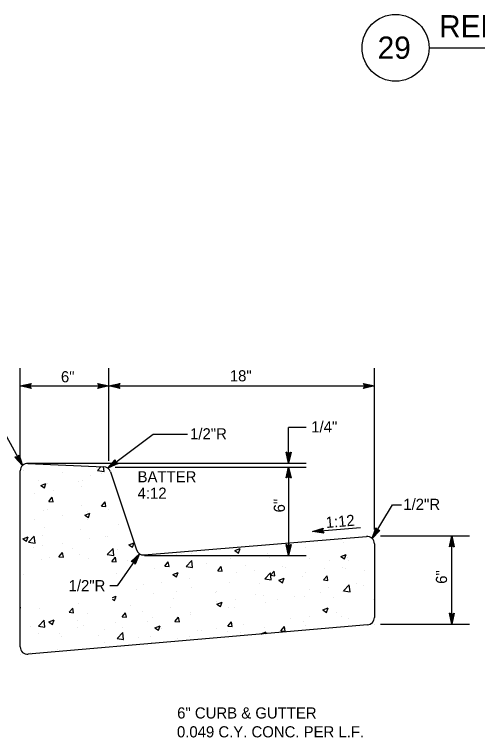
# Model space of a CAD drawing. Extents: x -119017 to -116080, y -104449 to -102845.
# Drawn here: x -118067.3 to -117818, y -104028.1 to -103638.5 of the extents above; entities that cross this region are included whole.
import ezdxf

# ---------------------------------------------------------------- set-up
doc = ezdxf.new("R2010")
doc.units = 0
for name, color, linetype in [('G-MARK', 7, 'Continuous'), ('G-TEXT', 7, 'Continuous'), ('Misc CnstDet(22)', 7, 'Continuous'), ('Nongeo Data(60)', 7, 'Continuous')]:
    doc.layers.add(name, color=color, linetype=linetype)

msp = doc.modelspace()

# ---------------------------------------------------------------- linework, layer by layer
at = {"layer": 'G-MARK'}
for p, q in [((-118064.22, -103876.84), (-118064.22, -103829.12)), ((-118016.53, -103879.03), (-118016.53, -103829.12)), ((-117873.56, -103916.09), (-117873.56, -103829.12)), ((-118064.22, -103838.66), (-118016.53, -103838.66)), ((-118016.53, -103838.66), (-117873.56, -103838.66)), ((-117919.75, -103880.19), (-117919.75, -103861.11)), ((-117910.24, -103861.11), (-117919.75, -103861.11)), ((-118060.88, -103880.19), (-117910.24, -103880.19)), ((-118013.19, -103882.35), (-117910.24, -103882.35)), ((-117919.75, -103882.35), (-117919.75, -103901.42)), ((-117919.75, -103891.88), (-117919.75, -103930)), ((-117906.83, -103917.18), (-117880.97, -103915.03)), ((-117870.22, -103919.4), (-117822.37, -103919.4)), ((-117831.88, -103967.06), (-117831.88, -103919.4)), ((-117997.3, -103930), (-117910.24, -103930)), ((-117870.22, -103967.06), (-117822.37, -103967.06))]:
    msp.add_line(p, q, dxfattribs=at)
for points in [[(-118063.03, -103881.5), (-118077.01, -103856.14), (-118081.48, -103856.14)], [(-118017.03, -103883.04), (-117992.64, -103864.59), (-117974.26, -103864.59)], [(-117874.84, -103920.81), (-117863.9, -103902.7), (-117858.93, -103902.7)], [(-118000.05, -103929.1), (-118012.09, -103946.39), (-118016.06, -103946.39)]]:
    msp.add_lwpolyline(points, dxfattribs=at)
at = {"layer": 'G-TEXT'}
for points in [[(-118058.32, -103839.98), (-118064.22, -103838.66), (-118058.32, -103837.35), (-118058.53, -103837.7), (-118062.85, -103838.66), (-118058.53, -103839.63), (-118058.73, -103839.28), (-118061.5, -103838.66), (-118058.74, -103838.05), (-118058.95, -103838.4), (-118060.14, -103838.66), (-118058.94, -103838.93), (-118059.1, -103838.66), (-118058.32, -103837.35), (-118059.1, -103838.66)], [(-118022.44, -103837.34), (-118016.53, -103838.66), (-118022.44, -103839.97), (-118022.23, -103839.62), (-118017.9, -103838.66), (-118022.23, -103837.69), (-118022.02, -103838.04), (-118019.25, -103838.66), (-118022.02, -103839.27), (-118021.81, -103838.92), (-118020.61, -103838.66), (-118021.81, -103838.39), (-118021.65, -103838.66), (-118022.44, -103839.97), (-118021.65, -103838.66)], [(-118010.63, -103839.98), (-118016.53, -103838.66), (-118010.63, -103837.35), (-118010.84, -103837.7), (-118015.16, -103838.66), (-118010.84, -103839.63), (-118011.05, -103839.28), (-118013.81, -103838.66), (-118011.05, -103838.05), (-118011.26, -103838.4), (-118012.45, -103838.66), (-118011.25, -103838.93), (-118011.42, -103838.66), (-118010.63, -103837.35), (-118011.42, -103838.66)], [(-117879.47, -103837.34), (-117873.56, -103838.66), (-117879.47, -103839.97), (-117879.26, -103839.62), (-117874.93, -103838.66), (-117879.26, -103837.69), (-117879.05, -103838.04), (-117876.28, -103838.66), (-117879.05, -103839.27), (-117878.84, -103838.92), (-117877.64, -103838.66), (-117878.84, -103838.39), (-117878.68, -103838.66), (-117879.47, -103839.97), (-117878.68, -103838.66)], [(-117918.43, -103874.28), (-117919.75, -103880.19), (-117921.06, -103874.28), (-117920.71, -103874.49), (-117919.75, -103878.82), (-117918.78, -103874.49), (-117919.13, -103874.7), (-117919.75, -103877.47), (-117920.36, -103874.7), (-117920.01, -103874.91), (-117919.75, -103876.11), (-117919.48, -103874.91), (-117919.75, -103875.07), (-117921.06, -103874.28), (-117919.75, -103875.07)], [(-118064.79, -103875.71), (-118063.03, -103881.5), (-118067.08, -103877.01), (-118066.67, -103877.02), (-118063.71, -103880.31), (-118065, -103876.07), (-118065.2, -103876.42), (-118064.37, -103879.14), (-118066.27, -103877.03), (-118065.86, -103877.04), (-118065.04, -103877.95), (-118065.4, -103876.77), (-118065.55, -103877.05), (-118067.08, -103877.01), (-118065.55, -103877.05)], [(-118011.55, -103880.48), (-118017.03, -103883.04), (-118013.15, -103878.39), (-118013.11, -103878.8), (-118015.95, -103882.2), (-118011.93, -103880.33), (-118012.31, -103880.18), (-118014.88, -103881.38), (-118013.06, -103879.2), (-118013.01, -103879.61), (-118013.8, -103880.55), (-118012.69, -103880.03), (-118012.98, -103879.91), (-118013.15, -103878.39), (-118012.98, -103879.91)], [(-117921.07, -103888.25), (-117919.75, -103882.35), (-117918.44, -103888.25), (-117918.79, -103888.04), (-117919.75, -103883.72), (-117920.72, -103888.04), (-117920.37, -103887.84), (-117919.75, -103885.07), (-117919.14, -103887.83), (-117919.49, -103887.62), (-117919.75, -103886.43), (-117920.02, -103887.63), (-117919.75, -103887.47), (-117918.44, -103888.25), (-117919.75, -103887.47)], [(-117900.83, -103917.93), (-117906.83, -103917.18), (-117901.08, -103915.31), (-117901.26, -103915.68), (-117905.47, -103917.05), (-117901.07, -103917.6), (-117901.31, -103917.27), (-117904.13, -103916.92), (-117901.43, -103916.05), (-117901.61, -103916.42), (-117902.77, -103916.79), (-117901.55, -103916.95), (-117901.74, -103916.69), (-117901.08, -103915.31), (-117901.74, -103916.69)], [(-117870.62, -103916.48), (-117874.84, -103920.81), (-117872.85, -103915.1), (-117872.67, -103915.46), (-117874.13, -103919.64), (-117871.02, -103916.47), (-117871.43, -103916.47), (-117873.41, -103918.5), (-117872.48, -103915.82), (-117872.29, -103916.19), (-117872.7, -103917.34), (-117871.84, -103916.46), (-117872.15, -103916.46), (-117872.85, -103915.1), (-117872.15, -103916.46)], [(-117833.2, -103925.31), (-117831.88, -103919.4), (-117830.57, -103925.31), (-117830.92, -103925.1), (-117831.87, -103920.77), (-117832.85, -103925.1), (-117832.5, -103924.89), (-117831.88, -103922.12), (-117831.27, -103924.89), (-117831.62, -103924.68), (-117831.88, -103923.48), (-117832.15, -103924.68), (-117831.88, -103924.52), (-117830.57, -103925.31), (-117831.88, -103924.52)], [(-117918.43, -103924.1), (-117919.75, -103930), (-117921.06, -103924.1), (-117920.71, -103924.31), (-117919.75, -103928.64), (-117918.78, -103924.31), (-117919.13, -103924.52), (-117919.75, -103927.29), (-117920.36, -103924.52), (-117920.01, -103924.73), (-117919.75, -103925.93), (-117919.48, -103924.72), (-117919.75, -103924.89), (-117921.06, -103924.1), (-117919.75, -103924.89)], [(-118004.48, -103933.22), (-118000.05, -103929.1), (-118002.32, -103934.71), (-118002.49, -103934.34), (-118000.83, -103930.23), (-118004.08, -103933.25), (-118003.67, -103933.27), (-118001.59, -103931.34), (-118002.65, -103933.97), (-118002.82, -103933.6), (-118002.36, -103932.46), (-118003.27, -103933.3), (-118002.95, -103933.32), (-118002.32, -103934.71), (-118002.95, -103933.32)], [(-117830.56, -103961.16), (-117831.88, -103967.06), (-117833.19, -103961.15), (-117832.84, -103961.37), (-117831.88, -103965.69), (-117830.91, -103961.36), (-117831.26, -103961.57), (-117831.88, -103964.34), (-117832.49, -103961.57), (-117832.14, -103961.79), (-117831.87, -103962.98), (-117831.61, -103961.78), (-117831.88, -103961.94), (-117833.19, -103961.15), (-117831.88, -103961.94)]]:
    msp.add_lwpolyline(points, close=True, dxfattribs=at)
at = {"layer": 'Misc CnstDet(22)'}
for p, q in [((-118016.53, -103838.66), (-118016.53, -103838.66)), ((-117873.56, -103838.66), (-117873.56, -103838.66)), ((-118064.22, -103880.19), (-118064.22, -103880.19)), ((-118064.22, -103880.19), (-118064.22, -103880.19)), ((-118064.22, -103880.19), (-118064.22, -103880.19)), ((-118022.63, -103884.16), (-118020.69, -103882.16)), ((-118019.1, -103884.69), (-118019.38, -103882.22)), ((-118016.53, -103882.35), (-118016.53, -103882.35)), ((-118016.53, -103882.35), (-118016.53, -103882.35)), ((-118016.53, -103882.35), (-118016.53, -103882.35)), ((-118016.53, -103882.35), (-118016.53, -103882.35)), ((-117919.75, -103882.35), (-117919.75, -103882.35)), ((-118062.66, -103884.16), (-118062.66, -103884.16)), ((-118041.46, -103885.07), (-118041.46, -103885.07)), ((-118022.63, -103884.16), (-118019.1, -103884.69)), ((-118020.25, -103885.97), (-118020.25, -103885.97)), ((-118054.28, -103889.51), (-118054.28, -103889.51)), ((-118030.61, -103889.7), (-118030.61, -103889.7)), ((-118026.38, -103887.1), (-118026.38, -103887.1)), ((-118053.15, -103892.23), (-118050.37, -103891.17)), ((-118053.15, -103892.23), (-118051.18, -103893.57)), ((-118051.24, -103892.7), (-118051.24, -103892.7)), ((-118051.18, -103893.57), (-118050.37, -103891.17)), ((-118049.56, -103891.07), (-118049.56, -103891.07)), ((-118033.08, -103890.38), (-118033.08, -103890.38)), ((-118031.29, -103893.07), (-118031.29, -103893.07)), ((-118056.28, -103896.39), (-118056.28, -103896.39)), ((-118046.34, -103895.07), (-118046.34, -103895.07)), ((-118048.9, -103900.86), (-118046.99, -103898.58)), ((-118048.9, -103900.86), (-118046.52, -103901.08)), ((-118046.52, -103901.08), (-118046.99, -103898.58)), ((-118020.41, -103903.36), (-118018.5, -103901.08)), ((-118018.07, -103903.58), (-118018.5, -103901.08)), ((-118010.72, -103900.14), (-118010.72, -103900.14)), ((-118051.75, -103905.89), (-118051.75, -103905.89)), ((-118049.37, -103905.24), (-118049.37, -103905.24)), ((-118031.11, -103902.92), (-118031.11, -103902.92)), ((-118020.41, -103903.36), (-118018.07, -103903.58)), ((-118016.66, -103905.46), (-118016.66, -103905.46)), ((-118041.74, -103908.74), (-118041.74, -103908.74)), ((-118029.45, -103908.24), (-118026.67, -103907.18)), ((-118029.45, -103908.24), (-118027.48, -103909.55)), ((-118028.17, -103906.14), (-118028.17, -103906.14)), ((-118027.48, -103909.55), (-118026.67, -103907.18)), ((-118056.78, -103910.74), (-118056.78, -103910.74)), ((-118028.01, -103910.8), (-118028.01, -103910.8)), ((-118011.19, -103913.34), (-118011.19, -103913.34)), ((-118051.18, -103914.78), (-118051.18, -103914.78)), ((-118031.58, -103916.15), (-118031.58, -103916.15)), ((-118062.82, -103921.03), (-118060.03, -103919.97)), ((-118062.82, -103921.03), (-118060.85, -103922.37)), ((-118060.85, -103922.37), (-118060.03, -103919.97)), ((-118059.75, -103922.84), (-118056.65, -103919.62)), ((-118056.22, -103923.41), (-118056.65, -103919.62)), ((-118052.21, -103919.12), (-118052.21, -103919.12)), ((-118027.1, -103921.12), (-118027.1, -103921.12)), ((-118018.5, -103919.53), (-118018.5, -103919.53)), ((-118017.16, -103919.81), (-118017.16, -103919.81)), ((-117873.56, -103919.4), (-117873.56, -103919.4)), ((-117873.56, -103919.4), (-117873.56, -103919.4)), ((-117831.88, -103919.4), (-117831.88, -103919.4)), ((-118059.75, -103922.84), (-118056.22, -103923.41)), ((-118052.18, -103924.41), (-118052.18, -103924.41)), ((-118041.68, -103923.5), (-118041.68, -103923.5)), ((-118005.75, -103924.22), (-118002.96, -103923.16)), ((-118005.75, -103924.22), (-118003.78, -103925.56)), ((-118003.78, -103925.56), (-118002.96, -103923.16)), ((-117890.01, -103923.16), (-117890.01, -103923.16)), ((-118057.09, -103925.53), (-118057.09, -103925.53)), ((-118043.4, -103930.75), (-118041.49, -103928.47)), ((-118041.02, -103930.94), (-118041.49, -103928.47)), ((-118035.89, -103926.44), (-118035.89, -103926.44)), ((-118017.35, -103929.41), (-118014.25, -103926.19)), ((-118014.69, -103927.35), (-118014.69, -103927.35)), ((-118013.81, -103929.97), (-118014.25, -103926.19)), ((-118011.69, -103926.56), (-118011.69, -103926.56)), ((-117977.54, -103928.88), (-117977.54, -103928.88)), ((-117972.28, -103929.13), (-117972.28, -103929.13)), ((-117962.5, -103926.91), (-117962.5, -103926.91)), ((-117948.68, -103927.41), (-117945.89, -103926.35)), ((-117948.68, -103927.41), (-117946.71, -103928.72)), ((-117946.71, -103928.72), (-117945.89, -103926.35)), ((-117931.04, -103928.94), (-117931.04, -103928.94)), ((-117910.4, -103925.97), (-117910.4, -103925.97)), ((-118052.68, -103932.35), (-118052.68, -103932.35)), ((-118048.71, -103930.88), (-118048.71, -103930.88)), ((-118043.4, -103930.75), (-118041.02, -103930.94)), ((-118032.08, -103929.38), (-118032.08, -103929.38)), ((-118027.51, -103931.79), (-118027.51, -103931.79)), ((-118017.35, -103929.41), (-118013.81, -103929.97)), ((-118014.91, -103933.23), (-118013, -103930.94)), ((-118014.91, -103933.23), (-118012.53, -103933.44)), ((-118012.53, -103933.44), (-118013, -103930.94)), ((-118006.34, -103932.66), (-118006.34, -103932.66)), ((-118000.65, -103930), (-118000.65, -103930)), ((-117987.48, -103930.19), (-117987.48, -103930.19)), ((-117980.17, -103929.44), (-117980.17, -103929.44)), ((-117974.97, -103935.98), (-117971.88, -103932.76)), ((-117971.44, -103936.54), (-117971.88, -103932.76)), ((-117951.08, -103930.04), (-117951.08, -103930.04)), ((-117951.08, -103931.47), (-117951.08, -103931.47)), ((-117929.88, -103930.91), (-117929.88, -103930.91)), ((-117919.75, -103930), (-117919.75, -103930)), ((-117908.71, -103931.82), (-117908.71, -103931.82)), ((-117897.8, -103932.66), (-117897.8, -103932.66)), ((-117891.61, -103930.57), (-117888.82, -103929.5)), ((-117891.61, -103930.57), (-117889.6, -103931.91)), ((-117889.6, -103931.91), (-117888.82, -103929.5)), ((-117887.85, -103931.35), (-117887.85, -103931.35)), ((-117887.51, -103932.72), (-117887.51, -103932.72)), ((-118012.56, -103933.48), (-118012.56, -103933.48)), ((-118003.34, -103933.41), (-118003.34, -103933.41)), ((-117986.42, -103935.73), (-117984.51, -103933.44)), ((-117986.42, -103935.73), (-117984.04, -103935.95)), ((-117985.14, -103933.57), (-117985.14, -103933.57)), ((-117984.04, -103935.95), (-117984.51, -103933.44)), ((-117974.97, -103935.98), (-117971.44, -103936.54)), ((-117971.47, -103934.26), (-117971.47, -103934.26)), ((-117963.94, -103934.48), (-117963.94, -103934.48)), ((-117957.93, -103938.23), (-117956.02, -103935.95)), ((-117955.55, -103938.42), (-117956.02, -103935.95)), ((-117942.73, -103935.35), (-117942.73, -103935.35)), ((-117922.88, -103935.98), (-117922.88, -103935.98)), ((-117921.53, -103936.26), (-117921.53, -103936.26)), ((-117900.33, -103937.13), (-117900.33, -103937.13)), ((-117890.48, -103936.38), (-117890.48, -103936.38)), ((-118062.63, -103940.07), (-118062.63, -103940.07)), ((-118012.16, -103939.79), (-118012.16, -103939.79)), ((-117992.11, -103937.26), (-117992.11, -103937.26)), ((-117982.04, -103940.2), (-117979.26, -103939.14)), ((-117982.04, -103940.2), (-117980.07, -103941.54)), ((-117980.07, -103941.54), (-117979.26, -103939.14)), ((-117957.93, -103938.23), (-117955.55, -103938.42)), ((-117947.86, -103939.26), (-117947.86, -103939.26)), ((-117937.92, -103937.95), (-117937.92, -103937.95)), ((-117932.57, -103942.58), (-117929.51, -103939.35)), ((-117929.07, -103943.11), (-117929.51, -103939.35)), ((-117929.44, -103940.7), (-117927.54, -103938.42)), ((-117929.44, -103940.7), (-117927.1, -103940.92)), ((-117927.1, -103940.92), (-117927.54, -103938.42)), ((-117910.87, -103939.17), (-117910.87, -103939.17)), ((-117900.99, -103943.2), (-117899.05, -103940.92)), ((-117898.61, -103943.42), (-117899.05, -103940.92)), ((-117889.17, -103937.23), (-117889.17, -103937.23)), ((-117879.13, -103938.04), (-117879.13, -103938.04)), ((-117987.98, -103944.55), (-117987.98, -103944.55)), ((-117972.94, -103942.54), (-117972.94, -103942.54)), ((-117951.55, -103944.7), (-117951.55, -103944.7)), ((-117932.57, -103942.58), (-117929.07, -103943.11)), ((-117931.51, -103942.17), (-117931.51, -103942.17)), ((-117924.97, -103943.39), (-117922.19, -103942.33)), ((-117924.97, -103943.39), (-117923, -103944.73)), ((-117923, -103944.73), (-117922.19, -103942.33)), ((-117912.34, -103941.2), (-117912.34, -103941.2)), ((-117900.99, -103943.2), (-117898.61, -103943.42)), ((-118001.4, -103948.42), (-118001.4, -103948.42)), ((-117997.93, -103945.86), (-117997.93, -103945.86)), ((-117971.97, -103947.48), (-117971.97, -103947.48)), ((-117935.51, -103945.2), (-117935.51, -103945.2)), ((-117908.24, -103948.33), (-117908.24, -103948.33)), ((-117898.3, -103947.02), (-117898.3, -103947.02)), ((-117890.2, -103949.14), (-117887.1, -103945.92)), ((-117886.66, -103949.67), (-117887.1, -103945.92)), ((-117883.26, -103945.05), (-117883.26, -103945.05)), ((-117879.66, -103945.95), (-117879.66, -103945.95)), ((-118014.53, -103952.68), (-118012.62, -103951.96)), ((-118013.44, -103954.36), (-118012.62, -103951.96)), ((-117992.58, -103950.46), (-117992.58, -103950.46)), ((-117980.2, -103949.33), (-117980.2, -103949.33)), ((-117958.99, -103950.21), (-117958.99, -103950.21)), ((-117958.65, -103949.17), (-117958.65, -103949.17)), ((-117937.79, -103951.11), (-117937.79, -103951.11)), ((-117933.32, -103951.64), (-117933.32, -103951.64)), ((-117916.59, -103951.99), (-117916.59, -103951.99)), ((-117911.37, -103952.39), (-117911.37, -103952.39)), ((-117902.83, -103949.92), (-117902.83, -103949.92)), ((-117890.98, -103949.61), (-117890.98, -103949.61)), ((-117890.2, -103949.14), (-117886.66, -103949.67)), ((-118033.04, -103955.8), (-118033.04, -103955.8)), ((-118014.53, -103953.61), (-118013.44, -103954.36)), ((-118012.66, -103953.02), (-118012.66, -103953.02)), ((-117981.82, -103953.15), (-117981.82, -103953.15)), ((-117958.34, -103956.21), (-117955.55, -103955.15)), ((-117958.34, -103956.21), (-117956.37, -103957.52)), ((-117958.31, -103954.93), (-117958.31, -103954.93)), ((-117956.37, -103957.52), (-117955.55, -103955.15)), ((-117948.36, -103953.61), (-117948.36, -103953.61)), ((-117931.98, -103955.37), (-117931.98, -103955.37)), ((-117925.97, -103953.9), (-117925.97, -103953.9)), ((-117895.39, -103952.89), (-117895.39, -103952.89)), ((-117874.19, -103953.8), (-117874.19, -103953.8)), ((-118064, -103958.34), (-118064.22, -103957.12)), ((-118064.22, -103958.3), (-118064, -103958.34)), ((-118053.65, -103958.77), (-118053.65, -103958.77)), ((-118037.89, -103960.62), (-118035.98, -103958.34)), ((-118035.52, -103960.84), (-118035.98, -103958.34)), ((-118004.96, -103957.12), (-118004.96, -103957.12)), ((-117998.43, -103960.21), (-117998.43, -103960.21)), ((-117983.39, -103958.21), (-117983.39, -103958.21)), ((-117952.05, -103957.93), (-117952.05, -103957.93)), ((-117949.14, -103957.9), (-117949.14, -103957.9)), ((-117901.27, -103959.37), (-117898.48, -103958.3)), ((-117901.27, -103959.37), (-117899.27, -103960.71)), ((-117899.27, -103960.71), (-117898.48, -103958.3)), ((-118037.89, -103960.62), (-118035.52, -103960.84)), ((-118028.14, -103961.09), (-118028.14, -103961.09)), ((-118009.4, -103963.12), (-118007.5, -103960.84)), ((-118009.4, -103963.12), (-118007.03, -103963.31)), ((-118008.37, -103961.53), (-118008.37, -103961.53)), ((-118007.03, -103963.31), (-118007.5, -103960.84)), ((-117993.08, -103963.68), (-117993.08, -103963.68)), ((-117980.92, -103965.59), (-117979.01, -103963.31)), ((-117978.54, -103965.81), (-117979.01, -103963.31)), ((-117972.44, -103960.71), (-117972.44, -103960.71)), ((-117972.32, -103961.87), (-117972.32, -103961.87)), ((-117918.69, -103964), (-117918.69, -103964)), ((-117908.74, -103962.68), (-117908.74, -103962.68)), ((-117893.7, -103960.71), (-117893.7, -103960.71)), ((-117891.45, -103962.81), (-117891.45, -103962.81)), ((-117887.67, -103963.84), (-117887.67, -103963.84)), ((-118058.44, -103968.09), (-118058.44, -103968.09)), ((-118054.47, -103968.09), (-118051.37, -103964.87)), ((-118054.47, -103968.09), (-118050.93, -103968.66)), ((-118051.53, -103966.94), (-118051.53, -103966.94)), ((-118050.93, -103968.66), (-118051.37, -103964.87)), ((-118051.31, -103965.06), (-118051.31, -103965.06)), ((-118048.77, -103965.84), (-118045.99, -103964.75)), ((-118048.77, -103965.84), (-118046.8, -103967.15)), ((-118048.49, -103966.78), (-118048.49, -103966.78)), ((-118046.8, -103967.15), (-118045.99, -103964.75)), ((-118033.45, -103964.81), (-118033.45, -103964.81)), ((-118030.32, -103967.81), (-118030.32, -103967.81)), ((-118013.13, -103966.25), (-118013.13, -103966.25)), ((-117995.46, -103965.84), (-117995.46, -103965.84)), ((-117991.7, -103969), (-117988.92, -103967.94)), ((-117989.73, -103970.34), (-117988.92, -103967.94)), ((-117980.92, -103965.59), (-117978.54, -103965.81)), ((-117952.43, -103968.09), (-117950.52, -103965.81)), ((-117952.43, -103968.09), (-117950.05, -103968.31)), ((-117950.05, -103968.31), (-117950.52, -103965.81)), ((-117943.77, -103967.28), (-117943.77, -103967.28)), ((-117911.84, -103965.62), (-117911.84, -103965.62)), ((-117910.81, -103967.81), (-117910.81, -103967.81)), ((-117873.56, -103967.06), (-117873.56, -103967.06)), ((-118054.15, -103972), (-118054.15, -103972)), ((-118033.51, -103969.03), (-118033.51, -103969.03)), ((-118018.63, -103969.81), (-118018.63, -103969.81)), ((-118012.09, -103974.69), (-118009, -103971.47)), ((-118009.12, -103968.72), (-118009.12, -103968.72)), ((-118008.56, -103975.22), (-118009, -103971.47)), ((-117991.7, -103969), (-117989.73, -103970.34)), ((-117987.92, -103969.59), (-117987.92, -103969.59)), ((-117968.75, -103970.59), (-117968.75, -103970.59)), ((-117966.72, -103970.5), (-117966.72, -103970.5)), ((-117958.81, -103969.28), (-117958.81, -103969.28)), ((-117952.52, -103971.13), (-117952.52, -103971.13)), ((-117945.52, -103971.41), (-117945.52, -103971.41)), ((-117934.63, -103972.19), (-117931.85, -103971.13)), ((-117934.63, -103972.19), (-117934.38, -103972.35)), ((-117933.98, -103971.78), (-117933.98, -103971.78)), ((-117932.48, -103968.59), (-117932.48, -103968.59)), ((-117932.2, -103972.16), (-117931.85, -103971.13)), ((-117923.94, -103970.59), (-117922.03, -103968.31)), ((-117923.94, -103970.59), (-117921.56, -103970.78)), ((-117921.56, -103970.78), (-117922.03, -103968.31)), ((-118043.15, -103972.25), (-118043.15, -103972.25)), ((-118041.77, -103973.78), (-118041.77, -103973.78)), ((-118021.97, -103973.16), (-118021.97, -103973.16)), ((-118012.09, -103974.69), (-118008.56, -103975.22)), ((-118008.87, -103975.88), (-118008.87, -103975.88)), ((-118000.77, -103974.03), (-118000.77, -103974.03)), ((-117993.83, -103973.88), (-117993.83, -103973.88)), ((-117979.57, -103974.94), (-117979.57, -103974.94)), ((-117972.91, -103973.94), (-117972.91, -103973.94)), ((-118018.82, -103977.16), (-118018.82, -103977.16)), ((-117993.55, -103976.91), (-117993.55, -103976.91)), ((-118064.22, -103983.63), (-118064.22, -103983.63)), ((-118058.94, -103982.45), (-118058.94, -103982.45)), ((-118043.9, -103980.48), (-118043.9, -103980.48))]:
    msp.add_line(p, q, dxfattribs=at)
for points in [[(-118060.06, -103880.38), (-118019.25, -103882.22)], [(-118064.22, -103979.29), (-118064.22, -103884.35)], [(-118015.66, -103884.94), (-118001.62, -103927.03)], [(-117997.52, -103929.75), (-117877.85, -103919.78)], [(-117873.56, -103923.72), (-117873.56, -103963.43)], [(-117877.19, -103967.4), (-118059.91, -103983.26)]]:
    msp.add_lwpolyline(points, dxfattribs=at)
for centre, start, end in [((-118060.25, -103884.34), 87.3974, 180), ((-118019.43, -103886.2), 18.435, 87.3974), ((-117877.53, -103923.73), 0, 94.7636), ((-117997.86, -103925.79), 198.435, 274.7636), ((-117877.53, -103963.43), 274.9602, 0), ((-118060.25, -103979.29), 180, 274.9602)]:
    msp.add_arc(centre, 3.97, start, end, dxfattribs=at)
at = {"layer": 'Nongeo Data(60)'}
msp.add_line((-117844.15, -103656.47), (-117599.79, -103656.47), dxfattribs=at)
msp.add_circle((-117862.15, -103656.47), 18, dxfattribs=at)

# ---------------------------------------------------------------- texts
at = {"layer": 'Misc CnstDet(22)'}
for s, height, p in [('REMOVABLE GUARD POST', 12, (-117838.72, -103650.85)), ('29', 12, (-117871.81, -103662.37)), ('6"', 6, (-118042.31, -103836.7)), ('18"', 6, (-117951.4, -103836.2)), ('1/2"R', 6, (-117972.79, -103867.44)), ('BATTER', 6, (-118001.05, -103890.6)), ('4:12', 6, (-118001.05, -103899.44)), ('1/2"R', 6, (-117857.99, -103905.44)), ('1/2"R', 6, (-118038.2, -103949.28)), ('6" CURB & GUTTER', 6, (-117979.74, -104017.88)), ('0.049 C.Y. CONC. PER L.F.', 6, (-117979.86, -104028.05))]:
    msp.add_text(s, height=height, dxfattribs=at).set_placement(p)
for s, rotation, p in [('1/4"', 0.001, (-117907.55, -103863.69)), ('6"', 90, (-117921.75, -103906.81)), ('1:12', 4.7636, (-117899.52, -103915.24)), ('6"', 90, (-117834.45, -103945.29))]:
    msp.add_text(s, height=6, rotation=rotation, dxfattribs=at).set_placement(p)

doc.saveas('drawing.dxf')
